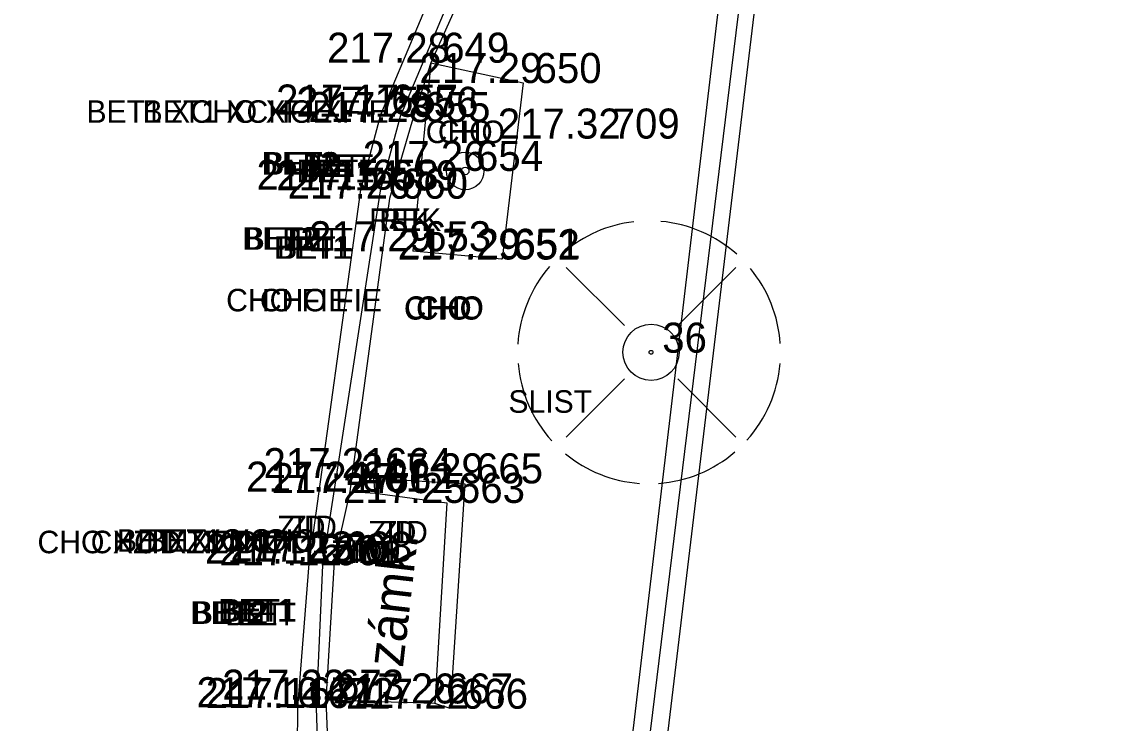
# Model space of a CAD drawing. Extents: x -471047 to -470889, y -1102859 to -1102000.
# Drawn here: x -471005.3 to -470990.69, y -1102654.36 to -1102645.03 of the extents above; entities that cross this region are included whole.
import ezdxf

# ---------------------------------------------------------------- set-up
doc = ezdxf.new("R2010")
doc.units = 0
for name, color, linetype in [('Vrstva 1', 7, 'Continuous'), ('Vrstva 16', 7, 'Continuous'), ('Vrstva 24', 7, 'Continuous'), ('Vrstva 3', 7, 'Continuous'), ('Vrstva 32', 7, 'Continuous'), ('Vrstva 34', 7, 'Continuous'), ('Vrstva 35', 7, 'Continuous'), ('Vrstva 36', 7, 'Continuous'), ('Vrstva 38', 7, 'Continuous'), ('Vrstva 5', 7, 'Continuous'), ('Vrstva 7', 7, 'Continuous'), ('Vrstva 8', 7, 'Continuous')]:
    doc.layers.add(name, color=color, linetype=linetype)

msp = doc.modelspace()

# ---------------------------------------------------------------- linework, layer by layer
at = {"layer": 'Vrstva 1'}
for points in [[(-471040.344, -1102858.385), (-471031.676, -1102846.187), (-471026.357, -1102838.629), (-471023.212, -1102833.975), (-471019.21, -1102827.465), (-471016.861, -1102823.272), (-471013.099, -1102815.912), (-471010.824, -1102810.955), (-471007.329, -1102802.292), (-471005.34, -1102796.515), (-471002.842, -1102787.838), (-471001.3, -1102780.997), (-471000.19, -1102774.713), (-470999.247, -1102768.204), (-470998.794, -1102764.784), (-470997.199, -1102751.812), (-470994.899, -1102732.807), (-470992.551, -1102713.262), (-470990.326, -1102694.887), (-470988.122, -1102676.57), (-470985.812, -1102657.305), (-470983.537, -1102638.407), (-470981.386, -1102620.622), (-470979.843, -1102608.014), (-470976.377, -1102579.253), (-470972.945, -1102550.69), (-470970.475, -1102530.206), (-470967.905, -1102508.801), (-470965.053, -1102485.131), (-470962.734, -1102465.9), (-470960.173, -1102444.812), (-470957.795, -1102425.103), (-470954.965, -1102401.839), (-470953.834, -1102392.574), (-470952.33, -1102379.985), (-470950.744, -1102366.853), (-470948.978, -1102352.106), (-470947.037, -1102335.844), (-470944.949, -1102318.462), (-470944.013, -1102310.745), (-470942.39, -1102297.267), (-470939.519, -1102273.45), (-470937.593, -1102257.43), (-470936.064, -1102244.81), (-470934.114, -1102228.634), (-470931.621, -1102207.856), (-470929.536, -1102190.857), (-470926.572, -1102166.31), (-470924.91, -1102152.663), (-470923.413, -1102140.333), (-470921.923, -1102127.669), (-470921.155, -1102120.084), (-470920.446, -1102109.574), (-470919.912, -1102099.137), (-470919.63, -1102088.981), (-470919.523, -1102081.193), (-470919.563, -1102070.395), (-470919.714, -1102064.236), (-470920.134, -1102054.704), (-470920.462, -1102047.615), (-470920.599, -1102044.52), (-470920.743, -1102041.873), (-470921.125, -1102034.455), (-470921.774, -1102030.337), (-470922.418, -1102027.787), (-470923.734, -1102023.93), (-470924.872, -1102021.434), (-470926.752, -1102018.182), (-470927.953, -1102016.45), (-470929.616, -1102014.424), (-470932.252, -1102011.756), (-470935.111, -1102009.425), (-470938.391, -1102007.371), (-470942.651, -1102005.401)], [(-471041.328, -1102857.18), (-471032.144, -1102844.242), (-471027.583, -1102837.763), (-471024.388, -1102833.028), (-471020.451, -1102826.6), (-471018.089, -1102822.378), (-471014.542, -1102815.445), (-471012.233, -1102810.418), (-471009.247, -1102803.108), (-471006.795, -1102796.098), (-471004.315, -1102787.532), (-471002.782, -1102780.723), (-471001.674, -1102774.458), (-471000.75, -1102768.095), (-471000.28, -1102764.601), (-470998.692, -1102751.741), (-470996.378, -1102732.635), (-470994.028, -1102713.058), (-470991.808, -1102694.749), (-470989.616, -1102676.447), (-470987.284, -1102657.013), (-470985.031, -1102638.272), (-470982.87, -1102620.431), (-470981.334, -1102607.933), (-470977.881, -1102579.263), (-470974.429, -1102550.492), (-470971.964, -1102530.054), (-470969.391, -1102508.607), (-470966.54, -1102484.984), (-470964.231, -1102465.853), (-470961.679, -1102444.752), (-470959.304, -1102425.078), (-470956.455, -1102401.634), (-470955.339, -1102392.489), (-470953.812, -1102379.71), (-470952.249, -1102366.808), (-470950.479, -1102352.023), (-470948.536, -1102335.868), (-470946.426, -1102318.233), (-470945.493, -1102310.531), (-470943.864, -1102297.013), (-470940.984, -1102273.071), (-470939.078, -1102257.195), (-470937.559, -1102244.684), (-470935.592, -1102228.353), (-470933.101, -1102207.653), (-470931.011, -1102190.57), (-470928.046, -1102166.021), (-470926.409, -1102152.578), (-470924.898, -1102140.121), (-470923.427, -1102127.544), (-470922.647, -1102119.826), (-470921.919, -1102109.229), (-470921.42, -1102099.134), (-470921.127, -1102089.016), (-470921.023, -1102081.453), (-470921.061, -1102070.468), (-470921.209, -1102064.314), (-470921.666, -1102053.966), (-470922.156, -1102043.345), (-470922.299, -1102039.934), (-470922.637, -1102034.36), (-470923.091, -1102031.241), (-470923.847, -1102028.247), (-470925.083, -1102024.594), (-470926.222, -1102022.086), (-470928.04, -1102018.943), (-470929.138, -1102017.357), (-470930.929, -1102015.175), (-470933.062, -1102013.049), (-470936.379, -1102010.368), (-470939.169, -1102008.662), (-470942.899, -1102006.906), (-470945.661, -1102005.908)], [(-471043.557, -1102855.955), (-471035.129, -1102844.026), (-471029.872, -1102836.499), (-471026.577, -1102831.578), (-471022.675, -1102825.415), (-471020.123, -1102821.053), (-471016.667, -1102814.59), (-471014.208, -1102809.45), (-471011.177, -1102802.451), (-471008.55, -1102795.333), (-471006.082, -1102787.209), (-471004.464, -1102780.376), (-471003.265, -1102774.167), (-471002.327, -1102767.948), (-471001.636, -1102762.527), (-471000.297, -1102751.605), (-470997.959, -1102732.524), (-470995.602, -1102712.802), (-470993.412, -1102694.623), (-470991.21, -1102676.17), (-470988.891, -1102656.857), (-470986.625, -1102638.083), (-470984.455, -1102620.195), (-470982.936, -1102607.733), (-470979.497, -1102579.223), (-470976.023, -1102550.279), (-470973.554, -1102529.822), (-470970.991, -1102508.497), (-470968.146, -1102484.787), (-470965.835, -1102465.72), (-470963.284, -1102444.529), (-470960.91, -1102424.942), (-470958.043, -1102401.343), (-470956.946, -1102392.356), (-470955.396, -1102379.408), (-470953.851, -1102366.636), (-470952.049, -1102351.733), (-470950.124, -1102335.611), (-470948.034, -1102318.083), (-470947.094, -1102310.328), (-470945.421, -1102296.51), (-470942.58, -1102272.848), (-470940.675, -1102256.948), (-470939.176, -1102244.526), (-470937.187, -1102228.174), (-470934.708, -1102207.467), (-470932.621, -1102190.433), (-470929.634, -1102165.778), (-470928.004, -1102152.415), (-470926.45, -1102139.595), (-470925.003, -1102127.418), (-470924.249, -1102119.695), (-470923.515, -1102109.093), (-470923.018, -1102099.069), (-470922.711, -1102088.911), (-470922.643, -1102081.356), (-470922.797, -1102070.414), (-470923.018, -1102064.454), (-470923.52, -1102053.203), (-470923.823, -1102047.529), (-470924.123, -1102041.506), (-470924.462, -1102037.486), (-470924.934, -1102031.904), (-470925.664, -1102028.672), (-470926.771, -1102025.506), (-470927.959, -1102022.914), (-470929.674, -1102020.028), (-470930.76, -1102018.498), (-470932.447, -1102016.478), (-470935.215, -1102013.816), (-470937.644, -1102011.98), (-470940.381, -1102010.371), (-470943.968, -1102008.669), (-470947.145, -1102007.524), (-470950.874, -1102006.74)], [(-471044.756, -1102855.056), (-471036.376, -1102843.177), (-471031.167, -1102835.741), (-471027.859, -1102830.8), (-471023.934, -1102824.593), (-471021.43, -1102820.312), (-471018.011, -1102813.91), (-471015.536, -1102808.75), (-471012.578, -1102801.897), (-471009.95, -1102794.77), (-471007.561, -1102786.914), (-471005.936, -1102780.074), (-471004.727, -1102773.818), (-471003.828, -1102767.827), (-471003.121, -1102762.345), (-471001.787, -1102751.467), (-470999.446, -1102732.348), (-470997.073, -1102712.539), (-470994.902, -1102694.521), (-470992.696, -1102676.023), (-470990.376, -1102656.68), (-470988.131, -1102638.071), (-470985.947, -1102620.018), (-470984.417, -1102607.512), (-470980.993, -1102579.08), (-470977.514, -1102550.137), (-470975.048, -1102529.649), (-470972.488, -1102508.37), (-470969.618, -1102484.508), (-470967.34, -1102465.669), (-470964.767, -1102444.39), (-470962.402, -1102424.781), (-470959.534, -1102401.193), (-470958.432, -1102392.151), (-470956.883, -1102379.208), (-470955.335, -1102366.424), (-470953.535, -1102351.506), (-470951.606, -1102335.399), (-470949.519, -1102317.94), (-470948.575, -1102310.159), (-470946.889, -1102296.144), (-470944.056, -1102272.618), (-470942.139, -1102256.659), (-470940.657, -1102244.341), (-470938.638, -1102227.749), (-470936.19, -1102207.298), (-470934.102, -1102190.255), (-470931.124, -1102165.639), (-470929.492, -1102152.254), (-470927.915, -1102139.252), (-470926.46, -1102127.103), (-470925.74, -1102119.604), (-470925.012, -1102108.913), (-470924.523, -1102099.054), (-470924.217, -1102088.866), (-470924.148, -1102081.334), (-470924.301, -1102070.391), (-470924.518, -1102064.43), (-470924.97, -1102054.435), (-470925.588, -1102041.569), (-470925.963, -1102035.313), (-470926.405, -1102032.225), (-470927.078, -1102029.198), (-470928.123, -1102026.148), (-470929.318, -1102023.558), (-470930.84, -1102020.97), (-470931.868, -1102019.515), (-470933.443, -1102017.605), (-470936.26, -1102014.885), (-470938.429, -1102013.255), (-470941.213, -1102011.639), (-470944.847, -1102009.927), (-470947.723, -1102008.912), (-470951.444, -1102008.161), (-470954.511, -1102007.931), (-470957.895, -1102008.041)]]:
    msp.add_spline(points, degree=3, dxfattribs=at)
at = {"layer": 'Vrstva 16'}
for p, q in [((-470997.276, -1102649.07), (-470998.052, -1102648.295)), ((-470996.566, -1102649.07), (-470995.792, -1102648.295)), ((-470997.276, -1102649.78), (-470998.052, -1102650.555)), ((-470996.566, -1102649.78), (-470995.792, -1102650.555))]:
    msp.add_line(p, q, dxfattribs=at)
for radius in [0.375, 0.025, 0.025]:
    msp.add_circle((-470996.921, -1102649.425), radius, dxfattribs=at)
for start, end in [(96.7144, 130.447), (48.1897, 84.9117), (139.23, 176.4602), (3.8615, 39.6013), (184.9408, 222.2827), (318.1086, 355.0481), (230.4703, 265.8356), (274.1732, 310.7861)]:
    msp.add_arc((-470996.947, -1102649.425), 1.75, start, end, dxfattribs=at)
at = {"layer": 'Vrstva 24'}
for radius in [0.25, 0.05]:
    msp.add_circle((-470999.395, -1102647.011), radius, dxfattribs=at)
at = {"layer": 'Vrstva 3'}
for p, q in [((-471000.593, -1102651.3), (-471000.613, -1102651.101)), ((-471000.613, -1102651.101), (-470999.401, -1102651.174)), ((-470999.401, -1102651.174), (-470999.597, -1102654.165)), ((-471000.593, -1102651.3), (-470999.639, -1102651.428)), ((-470999.639, -1102651.428), (-470999.798, -1102654.102)), ((-470999.597, -1102654.165), (-470999.798, -1102654.102))]:
    msp.add_line(p, q, dxfattribs=at)
at = {"layer": 'Vrstva 34'}
for p, q in [((-470999.85, -1102645.57), (-470999.85, -1102645.57)), ((-470998.62, -1102645.84), (-470998.62, -1102645.84)), ((-471000.53, -1102646.26), (-471000.53, -1102646.26)), ((-471000.26, -1102646.29), (-471000.26, -1102646.29)), ((-471000.1, -1102646.36), (-471000.1, -1102646.36)), ((-470997.58, -1102646.58), (-470997.58, -1102646.58)), ((-470999.4, -1102647.01), (-470999.4, -1102647.01)), ((-471000.79, -1102647.26), (-471000.79, -1102647.26)), ((-471000.53, -1102647.27), (-471000.53, -1102647.27)), ((-471000.4, -1102647.38), (-471000.4, -1102647.38)), ((-471000.09, -1102648.08), (-471000.09, -1102648.08)), ((-470998.9, -1102648.18), (-470998.9, -1102648.18)), ((-470998.91, -1102648.19), (-470998.91, -1102648.19)), ((-470996.92, -1102649.43), (-470996.92, -1102649.43)), ((-471000.61, -1102651.1), (-471000.61, -1102651.1)), ((-470999.4, -1102651.17), (-470999.4, -1102651.17)), ((-471000.93, -1102651.28), (-471000.93, -1102651.28)), ((-471000.59, -1102651.3), (-471000.59, -1102651.3)), ((-470999.64, -1102651.43), (-470999.64, -1102651.43)), ((-471001.48, -1102652.24), (-471001.48, -1102652.24)), ((-471001.29, -1102652.26), (-471001.29, -1102652.26)), ((-471001.14, -1102652.21), (-471001.14, -1102652.21)), ((-471001.63, -1102654.15), (-471001.63, -1102654.15)), ((-471001.38, -1102654.16), (-471001.38, -1102654.16)), ((-471001.25, -1102654.05), (-471001.25, -1102654.05)), ((-470999.8, -1102654.1), (-470999.8, -1102654.1)), ((-470999.6, -1102654.17), (-470999.6, -1102654.17))]:
    msp.add_line(p, q, dxfattribs=at)
at = {"layer": 'Vrstva 5'}
for p, q in [((-470997.35, -1102659.957), (-470995.292, -1102642.768)), ((-470999.515, -1102643.867), (-471000.525, -1102646.264)), ((-471000.525, -1102646.264), (-471000.787, -1102647.263)), ((-471000.787, -1102647.263), (-471001.478, -1102652.24)), ((-471001.478, -1102652.24), (-471001.626, -1102654.151)), ((-471001.626, -1102654.151), (-471001.64, -1102655.214))]:
    msp.add_line(p, q, dxfattribs=at)
at = {"layer": 'Vrstva 7'}
for p, q in [((-470997.816, -1102660.021), (-470995.777, -1102642.78)), ((-470999.19, -1102644.088), (-470999.852, -1102645.571)), ((-470999.852, -1102645.571), (-471000.104, -1102646.361)), ((-471000.104, -1102646.361), (-471000.404, -1102647.378)), ((-471000.404, -1102647.378), (-471000.933, -1102651.277)), ((-471000.933, -1102651.277), (-471001.138, -1102652.213)), ((-471001.138, -1102652.213), (-471001.252, -1102654.055)), ((-471001.252, -1102654.055), (-471001.2, -1102655.225))]:
    msp.add_line(p, q, dxfattribs=at)
at = {"layer": 'Vrstva 8'}
for p, q in [((-470997.603, -1102659.985), (-470995.499, -1102642.814)), ((-470999.306, -1102644.007), (-471000.263, -1102646.287)), ((-470999.852, -1102645.571), (-471000.093, -1102648.08)), ((-470999.852, -1102645.571), (-470998.623, -1102645.839)), ((-470998.623, -1102645.839), (-470998.904, -1102648.182)), ((-471000.263, -1102646.287), (-471000.526, -1102647.274)), ((-471000.526, -1102647.274), (-471001.293, -1102652.257)), ((-470998.906, -1102648.186), (-471000.093, -1102648.08)), ((-470998.904, -1102648.182), (-470998.906, -1102648.186)), ((-471000.933, -1102651.277), (-471000.593, -1102651.3)), ((-471001.293, -1102652.257), (-471001.379, -1102654.163)), ((-471001.379, -1102654.163), (-471001.346, -1102655.288)), ((-470999.798, -1102654.102), (-471001.252, -1102654.055))]:
    msp.add_line(p, q, dxfattribs=at)

# ---------------------------------------------------------------- texts
at = {"layer": 'Vrstva 32'}
msp.add_text('zámk.', height=0.5, rotation=83.44, dxfattribs=at).set_placement((-471000.225, -1102653.631))
at = {"layer": 'Vrstva 35'}
for s, p in [('BET1 XCHO XFIE', (-471004.438, -1102646.37)), ('BET1 XCHO XFIE', (-471003.69, -1102646.37)), ('CHO', (-470999.921, -1102646.64)), ('CHO', (-470999.759, -1102646.64)), ('BET2', (-471002.105, -1102647.06)), ('BET2', (-471002.071, -1102647.06)), ('BET1', (-471001.642, -1102647.16)), ('BET1', (-471001.6, -1102647.16)), ('BET', (-471001.56, -1102647.09)), ('BET', (-471001.399, -1102647.09)), ('REK', (-471000.675, -1102647.81)), ('REK', (-471000.539, -1102647.81)), ('BET2', (-471002.365, -1102648.06)), ('BET2', (-471002.331, -1102648.06)), ('BET1', (-471001.942, -1102648.18)), ('BET1', (-471001.9, -1102648.18)), ('BET', (-471001.83, -1102648.07)), ('BET', (-471001.669, -1102648.07)), ('CHO FIE', (-471002.578, -1102648.88)), ('CHO FIE', (-471002.129, -1102648.88)), ('CHO', (-471000.211, -1102648.99)), ('CHO', (-471000.201, -1102648.98)), ('CHO', (-471000.049, -1102648.99)), ('CHO', (-471000.039, -1102648.98)), ('SLIST', (-470998.82, -1102650.23)), ('ZID', (-471001.901, -1102651.9)), ('ZID', (-471001.749, -1102651.9)), ('ZID', (-471000.691, -1102651.97)), ('ZID', (-471000.539, -1102651.97)), ('CHO XZID XZID1', (-471005.09, -1102652.1)), ('CHO XZID XZID1', (-471004.382, -1102652.1)), ('BET1 XCHO', (-471004.031, -1102652.08)), ('BET1 XCHO', (-471003.645, -1102652.08)), ('ZID1', (-471001.182, -1102652.23)), ('ZID1', (-471001.14, -1102652.23)), ('BET2', (-471003.055, -1102653.04)), ('BET2', (-471003.021, -1102653.04)), ('BET1', (-471002.682, -1102653.01)), ('BET1', (-471002.64, -1102653.01)), ('BET', (-471002.59, -1102653.06)), ('BET', (-471002.429, -1102653.06))]:
    msp.add_text(s, height=0.3, dxfattribs=at).set_placement(p)
at = {"layer": 'Vrstva 36'}
for s, p in [(' 649', (-470999.85, -1102645.57)), (' 650', (-470998.62, -1102645.84)), (' 657', (-471000.53, -1102646.26)), (' 656', (-471000.26, -1102646.29)), (' 655', (-471000.1, -1102646.36)), (' 709', (-470997.58, -1102646.58)), (' 654', (-470999.4, -1102647.01)), (' 658', (-471000.79, -1102647.26)), (' 659', (-471000.53, -1102647.27)), (' 660', (-471000.4, -1102647.38)), (' 653', (-471000.09, -1102648.08)), (' 652', (-470998.91, -1102648.19)), (' 651', (-470998.9, -1102648.18)), (' 36', (-470996.92, -1102649.43)), (' 664', (-471000.61, -1102651.1)), (' 665', (-470999.4, -1102651.17)), (' 661', (-471000.93, -1102651.28)), (' 662', (-471000.59, -1102651.3)), (' 663', (-470999.64, -1102651.43)), (' 668', (-471001.14, -1102652.21)), (' 670', (-471001.48, -1102652.24)), (' 669', (-471001.29, -1102652.26)), (' 673', (-471001.25, -1102654.05)), (' 667', (-470999.8, -1102654.1)), (' 671', (-471001.63, -1102654.15)), (' 672', (-471001.38, -1102654.16)), (' 666', (-470999.6, -1102654.17))]:
    msp.add_text(s, height=0.4, dxfattribs=at).set_placement(p)
at = {"layer": 'Vrstva 38'}
for s, p in [('217.28 ', (-471001.234, -1102645.57)), ('217.29 ', (-471000.004, -1102645.84)), ('217.17 ', (-471001.913, -1102646.26)), ('217.15 ', (-471001.644, -1102646.29)), ('217.28 ', (-471001.484, -1102646.36)), ('217.32 ', (-470998.961, -1102646.58)), ('217.26 ', (-471000.76, -1102647.01)), ('217.15 ', (-471002.174, -1102647.26)), ('217.14 ', (-471001.912, -1102647.27)), ('217.26 ', (-471001.76, -1102647.38)), ('217.29 ', (-471001.474, -1102648.08)), ('217.29 ', (-471000.294, -1102648.19)), ('217.29 ', (-471000.284, -1102648.18)), ('217.21 ', (-471002.08, -1102651.1)), ('217.29 ', (-471000.784, -1102651.17)), ('217.24 ', (-471002.312, -1102651.28)), ('217.27 ', (-471001.973, -1102651.3)), ('217.25 ', (-471001.024, -1102651.43)), ('217.23 ', (-471002.523, -1102652.21)), ('217.12 ', (-471002.861, -1102652.24)), ('217.12 ', (-471002.671, -1102652.26)), ('217.22 ', (-471002.631, -1102654.05)), ('217.26 ', (-471001.16, -1102654.1)), ('217.10 ', (-471002.973, -1102654.15)), ('217.11 ', (-471002.85, -1102654.16)), ('217.22 ', (-471000.981, -1102654.17))]:
    msp.add_text(s, height=0.4, dxfattribs=at).set_placement(p)

doc.saveas('drawing.dxf')
